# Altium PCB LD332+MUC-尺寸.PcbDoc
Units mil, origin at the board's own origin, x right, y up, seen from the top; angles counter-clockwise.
Board outline 1246.06 x 1764.76 mil, 2 copper layers (Top Layer, Bottom Layer); 8 components, 0 nets, 38 pads, 0 vias.
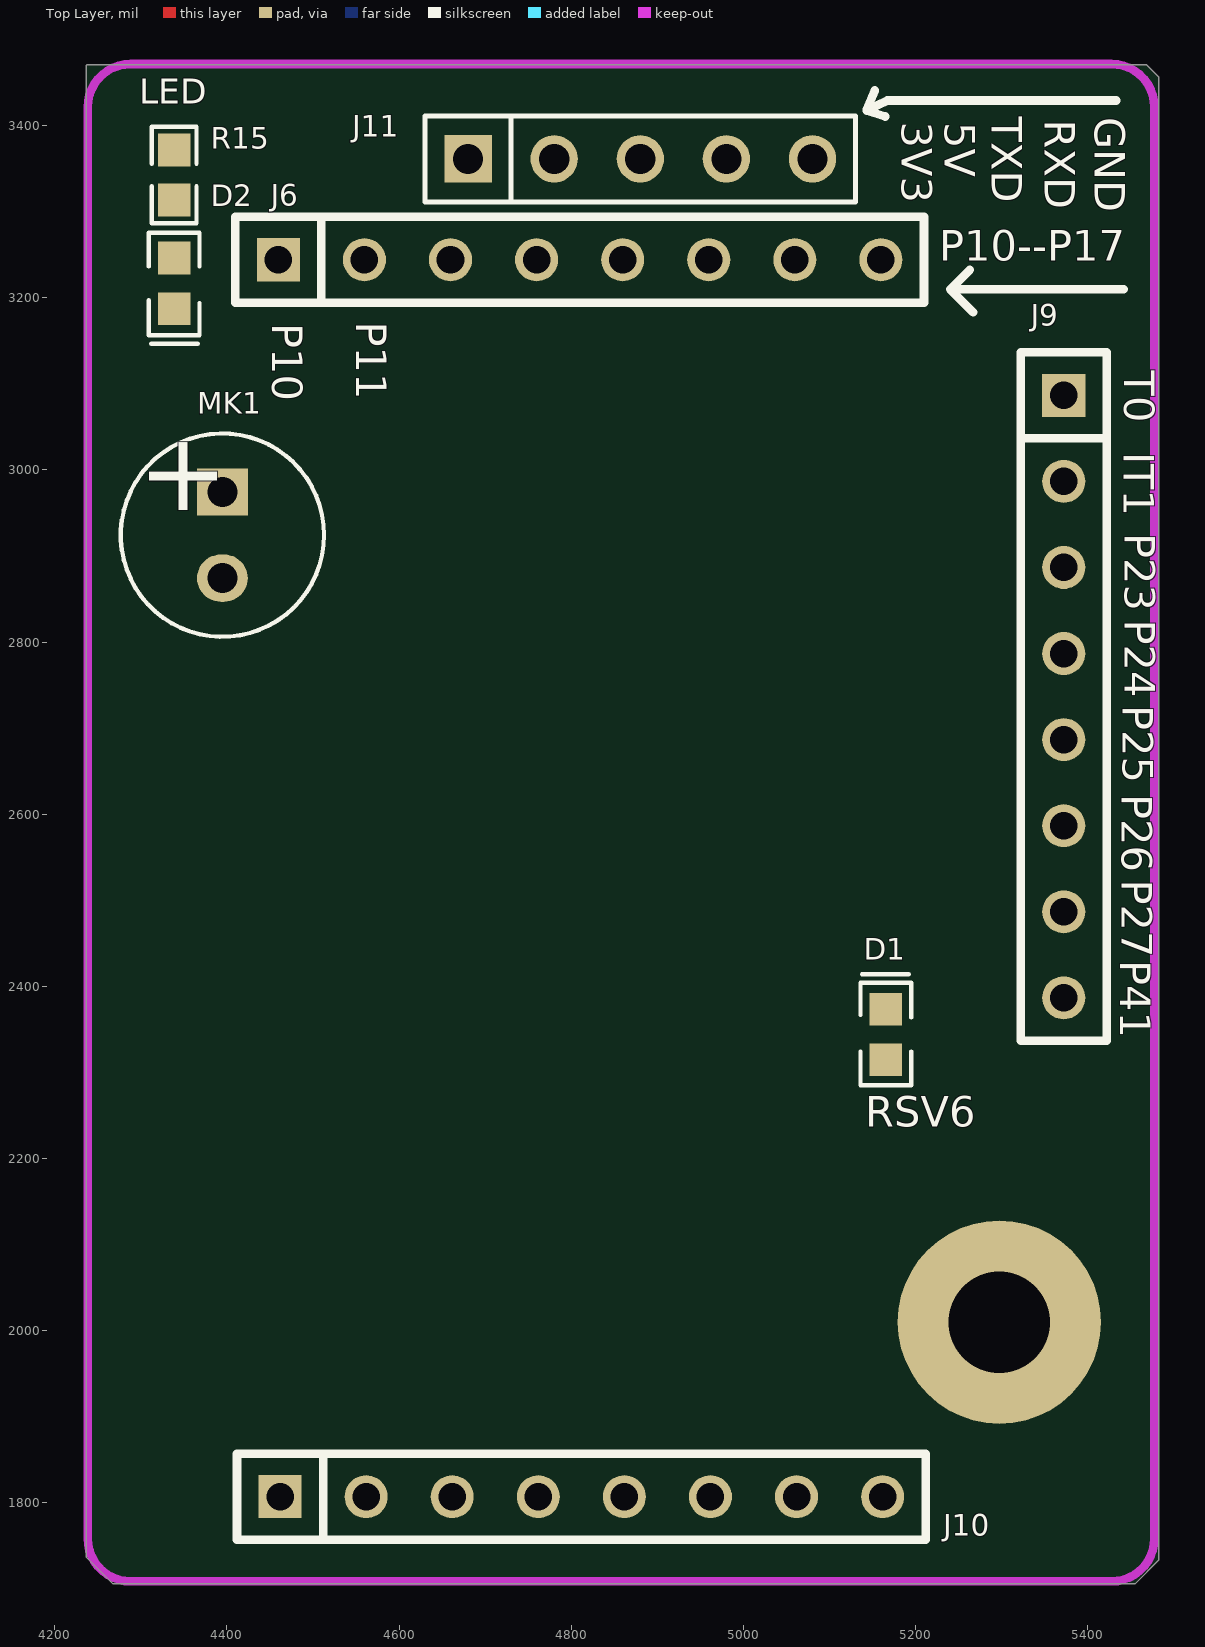
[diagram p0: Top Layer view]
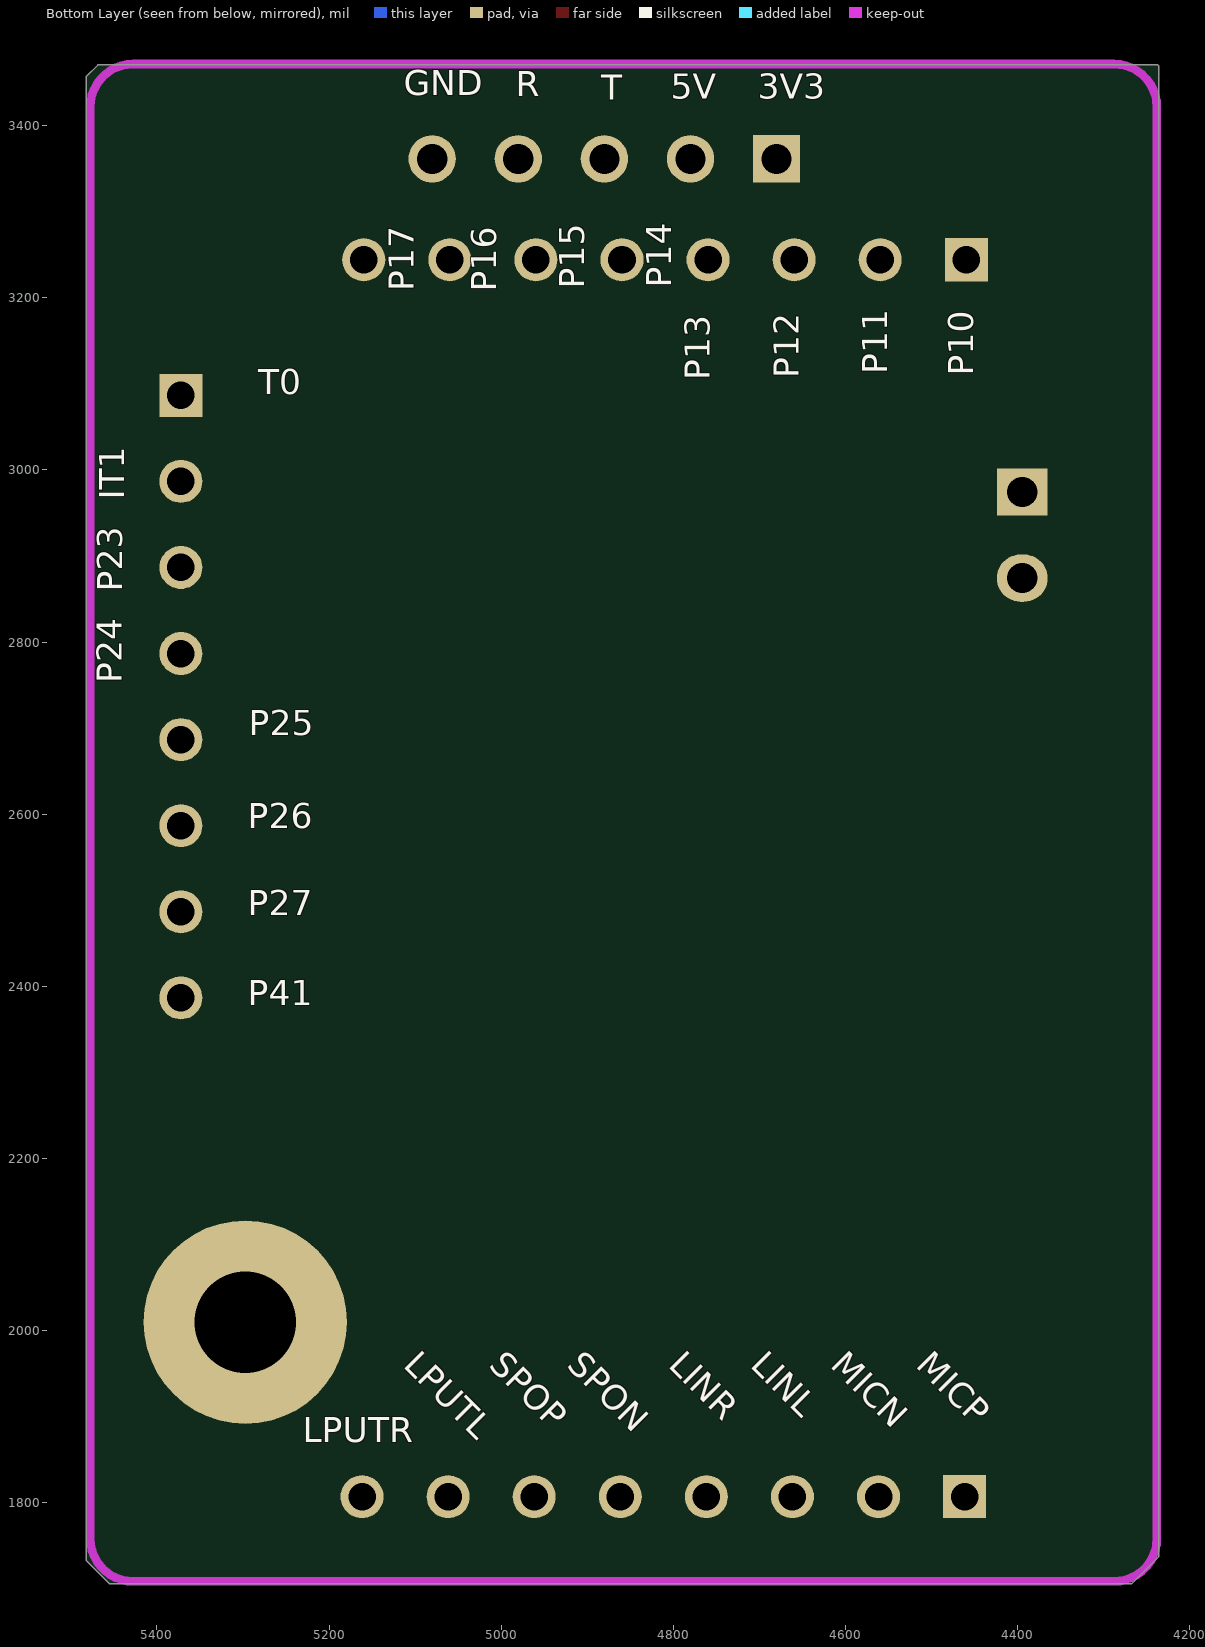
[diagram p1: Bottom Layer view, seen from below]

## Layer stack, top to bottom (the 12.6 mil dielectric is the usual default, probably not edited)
Top Layer: signal copper 1.4
Dielectric: dielectric 12.6, FR-4, Dk 4.8
Bottom Layer: signal copper 1.4

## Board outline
4237.2,3470.47 5468.5,3470.47 5482.28,3456.69 5482.28,1733.27 5454.72,1705.71 4267.72,1705.71 4236.22,1737.2 4236.22,3469.49 4237.2,3470.47

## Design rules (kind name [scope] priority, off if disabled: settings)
Clearance Clearance_2 [All] p1 off: gap=5
Clearance [All] p2: gap=7
Clearance Clearance_1 [All] p3: gap=15
ComponentClearance [All] p1: gap=0 collisioncheckmode=3 verticalgap=0 showdistances=FALSE
HoleSize [All] p1: absolutevalues=TRUE maxlimit=1000 minlimit=0 maxpercent=80.000 minpercent=20.000
HoleToHoleClearance [All] p1: gap=0 allowstackedmicrovias=TRUE
MinimumSolderMaskSliver [All] p1: minsoldermaskwidth=0
PlaneConnect [All] p1: planeconnectstyle=Direct reliefexpansion=20 reliefentries=4 reliefconductorwidth=10 reliefairgap=10
PolygonConnect [All] p1: connectstyle=Direct reliefconductorwidth=10 reliefentries=4 polygonreliefangle="90 Angle"
RoutingVias [All] p1: holewidth=28 width=50 viastyle="Through Hole" minholewidth=28 minwidth=50 maxholewidth=28 maxwidth=50
SilkToSilkClearance [All] p1: silktosilkclearance=0
SilkscreenOverComponentPads [All] p1: minsilkscreentomaskgap=0
SolderMaskExpansion [All] p1: expansion=4
Width [All] p1: maxlimit=100 minlimit=1 preferedwidth=10 minimp=50.000000 maximp=50.000000 favimp=50.000000
21 further rules are at their usual default settings.

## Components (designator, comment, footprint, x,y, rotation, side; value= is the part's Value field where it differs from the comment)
D1 "LED" 0603-LED 5165.35,2346.02 r90 top
D2 "LED" 0603-LED 4338.58,3214.57 r270 top
J6 "CON8" SIP8 4459.65,3244.09 r0 top
J9 "CON8" SIP8 5372.05,3086.61 r270 top
J10 "CON8" SIP8 4461.62,1807.09 r0 top
J11 "CON5" sip5 4680.12,3361.22 r0 top
MK1 "MICROPHONE2" MIC_6*5 4394.69,2924.21 r270 top
R15 "1K" 0603 4338.58,3342.52 r90 top

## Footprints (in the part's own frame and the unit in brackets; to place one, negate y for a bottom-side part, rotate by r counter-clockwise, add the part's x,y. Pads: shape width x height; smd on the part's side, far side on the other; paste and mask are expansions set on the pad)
0603 [mil]
  rect 38x38 smd: 1(-28.98,0) 2(28.98,0)
  silkscreen extent -56,-26 56,26
0603-LED [mil]
  rect 38x38 smd: 1(-31.44,0) 2(27.5,0)
  silkscreen extent -61,-30 68,30
MIC_6*5 [mil]
  rect 55x59.06 hole 35: 1(-50,0)
  oval 55x59.06 hole 35: 2(50,0)
  silkscreen extent -118,-118 118,118
sip5 [mil]
  rect 55x55 hole 35: 1(0,0)
  round 55 hole 35: 2(100,0) 3(200,0) 4(300,0) 5(400,0)
  silkscreen extent -50,-50 450,50
SIP8 [mil]
  rect 50x50 hole 32: 1(0,0)
  round 50 hole 32: 2(100,0) 3(200,0) 4(300,0) 5(400,0) 6(500,0) 7(600,0) 8(700,0)
  silkscreen extent -50,-50 750,50

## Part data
J6 J9 J10 J11: "Connector"
MK1: "Microphone"
R15: library part RES2

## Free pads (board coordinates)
  round 236.22 hole 118.11: 0(5297.24,2009.85)

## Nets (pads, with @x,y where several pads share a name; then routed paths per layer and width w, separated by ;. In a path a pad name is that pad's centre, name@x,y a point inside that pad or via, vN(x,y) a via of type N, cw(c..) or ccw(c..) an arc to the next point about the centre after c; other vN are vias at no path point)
pads on no net: D1.1 D1.2 D2.1 D2.2 J6.1 J6.2 J6.3 J6.4 J6.5 J6.6 J6.7 J6.8 J9.1 J9.2 J9.3 J9.4 J9.5 J9.6 J9.7 J9.8 J10.1 J10.2 J10.3 J10.4 J10.5 J10.6 J10.7 J10.8 J11.1 J11.2 J11.3 J11.4 J11.5 MK1.1 MK1.2 R15.1 R15.2

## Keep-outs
Keep-Out Layer:
  lines w10: 4238.19,1758.66 ccw(c4288.19,1758.66) 4288.19,1708.66 5427.36,1708.66 ccw(c5427.36,1758.66) 5477.36,1758.66 5477.36,3421.46 ccw(c5427.36,3421.46) 5427.36,3471.46 4288.19,3471.46 ccw(c4288.19,3421.46) 4238.19,3421.46 4238.19,1758.66

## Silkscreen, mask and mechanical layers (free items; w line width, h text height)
Top Overlay:
  lines w10: 5152.56,3440.94 5143.15,3417.49 ; 5164.63,3410.51 5143.15,3417.49 ; 5262.8,3232.28 5240.16,3209.65 ; 5266.73,3183.07 5240.16,3209.65 ; 5433.07,3429.13 5167.32,3429.13 5143.15,3417.49 ; 5441.93,3209.65 5240.16,3209.65
  text "LED" at 4298.23,3415.35 h50
  text "TXD" at 5276.57,3410.43 h60 r270
  text "GND" at 5396.65,3409.45 h60 r270
  text "RXD" at 5338.58,3406.5 h60 r270
  text "3V3" at 5172.24,3404.53 h60 r270
  text "5V" at 5222.44,3403.54 h60 r270
  text "P10--P17" at 5227.36,3231.3 h60
  text "P11" at 4538.39,3172.24 h60 r270
  text "P10" at 4440.94,3170.28 h60 r270
  text "T0" at 5430.91,3115.16 h60 r270
  text "IT1" at 5429.92,3020.67 h60 r270
  text "P23" at 5431.1,2926.18 h60 r270
  text "P24" at 5431.1,2825.79 h60 r270
  text "P25" at 5428.94,2726.38 h60 r270
  text "P26" at 5427.95,2623.03 h60 r270
  text "P27" at 5427.95,2523.62 h60 r270
  text "P41" at 5425.98,2430.12 h60 r270
  text "RSV6" at 5141.73,2225.39 h60
Bottom Overlay:
  text "GND" at 5113.19,3425.2 h50
  text "R" at 4983.27,3424.21 h50
  text "3V3" at 4701.77,3421.26 h50
  text "5V" at 4803.15,3421.26 h50
  text "T" at 4883.86,3420.28 h50
  text "P14" at 4792.32,3211.61 h50 r270
  text "P15" at 4893.7,3210.63 h50 r270
  text "P17" at 5091.54,3207.68 h50 r270
  text "P16" at 4996.06,3206.69 h50 r270
  text "P11" at 4541.34,3111.22 h50 r270
  text "P10" at 4441.93,3109.25 h50 r270
  text "P12" at 4644.69,3106.3 h50 r270
  text "P13" at 4748.03,3104.33 h50 r270
  text "T0" at 5282.48,3077.76 h50
  text "IT1" at 5428.15,2965.55 h50 r270
  text "P23" at 5430.12,2858.27 h50 r270
  text "P24" at 5431.1,2751.97 h50 r270
  text "P25" at 5293.31,2682.09 h50
  text "P26" at 5294.29,2573.82 h50
  text "P27" at 5294.29,2472.44 h50
  text "P41" at 5294.29,2368.11 h50
  text "MICP" at 4526.57,1951.77 h50 r45
  text "MICN" at 4625.98,1951.77 h50 r45
  text "LINL" at 4718.5,1951.77 h50 r45
  text "LINR" at 4813.98,1951.77 h50 r45
  text "SPON" at 4932.09,1951.77 h50 r45
  text "SPOP" at 5022.64,1951.77 h50 r45
  text "LPUTL" at 5122.05,1951.77 h50 r45
  text "LPUTR" at 5230.31,1860.24 h50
